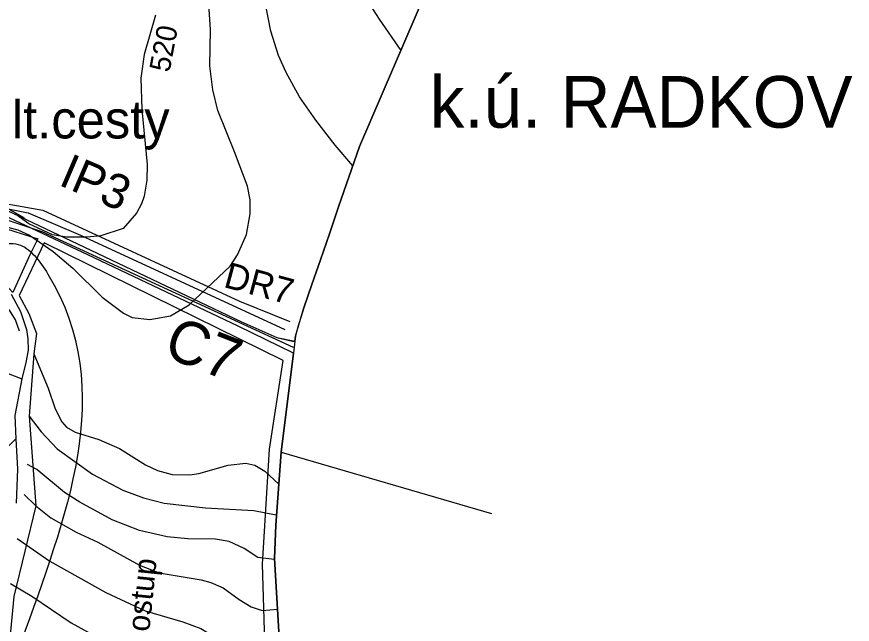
# Model space of a CAD drawing. Extents: x -684583 to -680383, y -1157874 to -1154904.
# Drawn here: x -682795.6 to -682310.9, y -1156657.4 to -1156304.8 of the extents above; entities that cross this region are included whole.
import ezdxf

# ---------------------------------------------------------------- set-up
doc = ezdxf.new("R2010")
doc.units = 0
for name, color, linetype in [('01_OBVOD PÚ', 7, 'Continuous'), ('01_SPRÁV_HRANICE', 7, 'Continuous'), ('01_VRSTEVNICE', 7, 'Continuous'), ('02_KULTURY NÁVRH', 7, 'Continuous'), ('02_KULTURY STAV', 7, 'Continuous'), ('03_PC_NÁVRH', 7, 'Continuous'), ('03_PC_OBJEKTY_NÁVRH', 7, 'Continuous'), ('03_PC_POPIS_NÁVRH', 7, 'Continuous'), ('04_ZPF_OP_ORGAN', 7, 'Continuous'), ('06_BIOGEOGRAFIE', 7, 'Continuous'), ('06_REVITALIZACE', 7, 'Continuous'), ('06_ÚSES_IP', 7, 'Continuous')]:
    doc.layers.add(name, color=color, linetype=linetype)

msp = doc.modelspace()

# ---------------------------------------------------------------- linework, layer by layer
at = {"layer": '01_OBVOD PÚ'}
for points in [[(-682557.32, -1156288.22), (-682596.72, -1156380.07), (-682608.85, -1156415.21), (-682614.21, -1156430.78), (-682619.39, -1156445.85), (-682624.47, -1156460.14), (-682629.07, -1156473.67), (-682632.75, -1156485.61), (-682633.78, -1156490.12), (-682634.17, -1156493.17), (-682635.01, -1156500.02), (-682642.14, -1156557.42)], [(-682642.14, -1156557.42), (-682645.25, -1156599.9), (-682646.11, -1156619.18), (-682640.57, -1156710.88), (-682641.16, -1156744.34), (-682654.58, -1156802.96), (-682670.79, -1156859.33), (-682678.39, -1156891.56), (-682695.23, -1156914.21), (-682697.53, -1156916.41), (-682704.08, -1156912.85), (-682712.58, -1156940.81), (-682727.9, -1157004.18), (-682712.59, -1157046.25), (-682692.26, -1157098.17), (-682680.36, -1157125.02), (-682671.31, -1157151.47), (-682668.33, -1157170.08), (-682667.92, -1157187.26), (-682669.24, -1157225.79), (-682669.43, -1157229.79), (-682672.44, -1157241.72), (-682587.6, -1157329.91)]]:
    msp.add_lwpolyline(points, dxfattribs=at)
at = {"layer": '01_SPRÁV_HRANICE'}
for points in [[(-682557.32, -1156288.22), (-682596.72, -1156380.07), (-682608.85, -1156415.21), (-682614.21, -1156430.78), (-682619.39, -1156445.85), (-682624.47, -1156460.14), (-682629.07, -1156473.67), (-682632.75, -1156485.61), (-682633.78, -1156490.12), (-682634.17, -1156493.17), (-682635.01, -1156500.02), (-682642.14, -1156557.42)], [(-682642.14, -1156557.42), (-682645.25, -1156599.9), (-682646.11, -1156619.18), (-682640.57, -1156710.88), (-682641.16, -1156744.34), (-682654.58, -1156802.96), (-682670.79, -1156859.33), (-682678.39, -1156891.56), (-682695.23, -1156914.21), (-682697.53, -1156916.41), (-682704.08, -1156912.85), (-682712.58, -1156940.81), (-682727.9, -1157004.18), (-682712.59, -1157046.25), (-682692.26, -1157098.17), (-682680.36, -1157125.02), (-682671.31, -1157151.47), (-682668.33, -1157170.08), (-682667.92, -1157187.26), (-682669.24, -1157225.79), (-682669.43, -1157229.79), (-682672.44, -1157241.72), (-682587.6, -1157329.91)], [(-682642.14, -1156557.42), (-682520.18, -1156593.07)]]:
    msp.add_lwpolyline(points, dxfattribs=at)
at = {"layer": '01_VRSTEVNICE'}
for points in [[(-682745.52, -1156093.9), (-682737.96, -1156090.76), (-682731.82, -1156090.48), (-682727.69, -1156091.9), (-682722.12, -1156095.33), (-682705.43, -1156113.73), (-682691.17, -1156131.28), (-682682.47, -1156143.26), (-682670.49, -1156161.66), (-682629.69, -1156229.13), (-682597.45, -1156287.18), (-682585.33, -1156306.3), (-682572.83, -1156324.37)], [(-682600.59, -1156391.28), (-682610.86, -1156379.33), (-682622.13, -1156364.93), (-682631.54, -1156351.23), (-682639.25, -1156337.25), (-682643.67, -1156327.27), (-682648.23, -1156313.29), (-682654.65, -1156279.34), (-682659.93, -1156261.22), (-682667.35, -1156244.82), (-682674.34, -1156232.12), (-682684.18, -1156218.72), (-682703.58, -1156199.46), (-682710.28, -1156191.9), (-682725.97, -1156171.36), (-682734.82, -1156162.94), (-682739.95, -1156159.8), (-682748.51, -1156156.09), (-682759.5, -1156154.1), (-682766.77, -1156155.52), (-682772.48, -1156158.52), (-682778.18, -1156163.37), (-682789.45, -1156159.23)], [(-682805.57, -1156425.83), (-682795.01, -1156428.4), (-682788.17, -1156431.54), (-682774.47, -1156441.1), (-682763.06, -1156450.8), (-682746.09, -1156467.49), (-682733.68, -1156476.9), (-682728.54, -1156479.33), (-682718.27, -1156480.47), (-682706.29, -1156478.33), (-682695.45, -1156472.05), (-682671.77, -1156449.51), (-682667.49, -1156442.95), (-682662.35, -1156431.11), (-682660.07, -1156419.13), (-682660.07, -1156411.14), (-682661.79, -1156403.15), (-682669.2, -1156383.18), (-682678.9, -1156359.22), (-682681.75, -1156347.24), (-682683.61, -1156333.26), (-682683.18, -1156312.15), (-682684.89, -1156286.19)], [(-682715.13, -1156303.87), (-682721.7, -1156326.7), (-682723.55, -1156340.39), (-682722.98, -1156358.65), (-682719.84, -1156390.6), (-682720.13, -1156399.73), (-682721.7, -1156408.86), (-682723.12, -1156413.42), (-682726.1, -1156418.88), (-682733.92, -1156427.73), (-682746.8, -1156431.97), (-682754.79, -1156432.68), (-682766.77, -1156432.68), (-682774.76, -1156431.4), (-682788.45, -1156424.98), (-682796.3, -1156419.41)], [(-682793.87, -1156487.31), (-682796.3, -1156480.75), (-682799.72, -1156475.19), (-682804.29, -1156469.91), (-682806.71, -1156468.34), (-682814.7, -1156465.35), (-682819.83, -1156464.92), (-682825.11, -1156465.63)], [(-682785.65, -1156500.47), (-682777.33, -1156520.41), (-682773.19, -1156532.39), (-682769.34, -1156539.95), (-682766.77, -1156543.09), (-682761.64, -1156545.94), (-682747.94, -1156550.22), (-682735.96, -1156555.35), (-682720.84, -1156564.77), (-682713.99, -1156568.19), (-682705.43, -1156570.47), (-682695.16, -1156570.62), (-682690.03, -1156569.9), (-682672.91, -1156565.05), (-682662.64, -1156563.91), (-682657.51, -1156565.05), (-682651.66, -1156568.48), (-682643.5, -1156576.03)], [(-682788.37, -1156536.68), (-682781.46, -1156545.65), (-682772.19, -1156555.64), (-682751.65, -1156570.33), (-682733.96, -1156579.6), (-682721.98, -1156584.03), (-682710, -1156587.02), (-682686.04, -1156589.88), (-682658.08, -1156591.3), (-682644.98, -1156593.84)], [(-682646.14, -1156619.75), (-682655.79, -1156618.55), (-682663.64, -1156613.41), (-682672.34, -1156609.28), (-682680.33, -1156607.99), (-682696.3, -1156607.71), (-682708.29, -1156606.56), (-682724.26, -1156603), (-682740.24, -1156596.72), (-682758.93, -1156586.59), (-682767.77, -1156580.89), (-682783.89, -1156567.48), (-682789.34, -1156564.7)], [(-682791.23, -1156582.13), (-682784.46, -1156588.73), (-682775.76, -1156595.58), (-682761.07, -1156604), (-682748.51, -1156609.7), (-682724.26, -1156623.11), (-682712.85, -1156627.53), (-682688.6, -1156631.53), (-682682.9, -1156633.1), (-682675.91, -1156636.23), (-682666.63, -1156643.08), (-682659.5, -1156647.22), (-682653.23, -1156649.36), (-682644.33, -1156648.57)], [(-682795.26, -1156607.53), (-682776.33, -1156620.69), (-682743.95, -1156638.94), (-682721.12, -1156649.5), (-682699.16, -1156655.92), (-682688.74, -1156659.91), (-682666.63, -1156673.32), (-682657.79, -1156674.46), (-682654.65, -1156673.75), (-682651.23, -1156671.47), (-682647.66, -1156670.61), (-682645.38, -1156673.32), (-682644.81, -1156677.6), (-682644.95, -1156690.44), (-682640.49, -1156712.13)], [(-682799.14, -1156633.78), (-682786.88, -1156641.08), (-682763.92, -1156656.63), (-682743.38, -1156668.04), (-682727.4, -1156674.6), (-682711.42, -1156679.74), (-682687.46, -1156686.02), (-682675.05, -1156691.01), (-682666.35, -1156697.29), (-682664.21, -1156699.57), (-682660.07, -1156706.41), (-682658.36, -1156710.98), (-682656.65, -1156720.11), (-682657.51, -1156744.93), (-682655.51, -1156761.9), (-682655.51, -1156767.47), (-682657.51, -1156777.74), (-682660.5, -1156786.3), (-682661.93, -1156792.86), (-682662.88, -1156799.77), (-682662.11, -1156829.16)]]:
    msp.add_lwpolyline(points, dxfattribs=at)
at = {"layer": '02_KULTURY NÁVRH'}
for points in [[(-682887.91, -1156417.72), (-682866.23, -1156419.79), (-682828.98, -1156422.33), (-682806.49, -1156426.37), (-682783.26, -1156433.67), (-682787.89, -1156443.08), (-682788.73, -1156444.69), (-682797.87, -1156464.81), (-682800.21, -1156462.31), (-682802.73, -1156459.5), (-682869.24, -1156422.91), (-682878.07, -1156420.23)], [(-682811.55, -1156507.67), (-682792.62, -1156514.96), (-682796.58, -1156536.16), (-682796.03, -1156549.68), (-682806.13, -1156559.58), (-682825.6, -1156557.59), (-682824.2, -1156541.34)]]:
    msp.add_lwpolyline(points, close=True, dxfattribs=at)
at = {"layer": '02_KULTURY STAV'}
for points in [[(-682837.34, -1156293.13), (-682860.97, -1156340.11), (-682865.88, -1156349.21), (-682879.26, -1156381.53), (-682886.9, -1156409.8), (-682882.56, -1156409.71), (-682869.55, -1156406.81), (-682851.47, -1156397.34), (-682840.47, -1156400.15), (-682828.26, -1156404.5), (-682752.66, -1156440.28), (-682665.48, -1156481.67), (-682644.77, -1156490.96), (-682634.17, -1156493.17), (-682633.78, -1156490.12), (-682629.07, -1156473.67), (-682624.47, -1156460.14), (-682619.39, -1156445.85), (-682614.21, -1156430.78), (-682608.85, -1156415.21), (-682596.72, -1156380.07), (-682557.32, -1156288.22)], [(-682640.57, -1156710.88), (-682646.11, -1156619.18), (-682645.25, -1156599.9), (-682642.14, -1156557.42), (-682635.01, -1156500.02), (-682667.07, -1156484.3), (-682754.25, -1156442.99), (-682829.25, -1156407.8)], [(-682798.7, -1156465.79), (-682793.43, -1156475.86), (-682789.98, -1156486.39), (-682789.16, -1156491.7), (-682788.94, -1156498.27), (-682790.31, -1156505.5), (-682792.62, -1156514.96), (-682796.58, -1156536.16)], [(-682798.7, -1156465.79), (-682793.43, -1156475.86), (-682789.98, -1156486.39), (-682789.16, -1156491.7), (-682788.94, -1156498.27), (-682790.31, -1156505.5), (-682792.62, -1156514.96), (-682796.58, -1156536.16)], [(-682796.03, -1156549.68), (-682795.1, -1156567.41), (-682795.87, -1156587.1)], [(-682796.03, -1156549.68), (-682795.1, -1156567.41), (-682795.87, -1156587.1)]]:
    msp.add_lwpolyline(points, dxfattribs=at)
msp.add_lwpolyline([(-682889.47, -1156417.03), (-682886.9, -1156409.8), (-682885.02, -1156409.17), (-682882.56, -1156409.71), (-682869.55, -1156406.81), (-682851.47, -1156397.34), (-682840.47, -1156400.15), (-682828.26, -1156404.5), (-682752.66, -1156440.28), (-682665.48, -1156481.67), (-682644.77, -1156490.96), (-682635.67, -1156493), (-682634.17, -1156493.17), (-682635.01, -1156500.02), (-682667.07, -1156484.3), (-682754.25, -1156442.99), (-682829.25, -1156407.8), (-682850.76, -1156400.72), (-682868.28, -1156409.71), (-682880.84, -1156413.58), (-682887.91, -1156417.72)], close=True, dxfattribs=at)
at = {"layer": '03_PC_NÁVRH'}
msp.add_lwpolyline([(-682887.94, -1156412.25), (-682866.49, -1156415.4), (-682828.6, -1156417.26), (-682802.44, -1156422.27), (-682780.99, -1156429.42), (-682635.3, -1156496.52)], dxfattribs=at)
at = {"layer": '03_PC_OBJEKTY_NÁVRH'}
msp.add_lwpolyline([(-682878.05, -1156408.2), (-682845.44, -1156408.2), (-682823.88, -1156411.7), (-682788.84, -1156418.72), (-682758.65, -1156431.66), (-682640.05, -1156486.4)], dxfattribs=at)
at = {"layer": '04_ZPF_OP_ORGAN'}
msp.add_lwpolyline([(-682779.67, -1156436.1), (-682794.2, -1156466.69), (-682788.61, -1156477.13), (-682784.14, -1156488.69), (-682785.65, -1156500.47), (-682788.37, -1156536.68), (-682784.46, -1156588.73), (-682797.19, -1156641.23), (-682810.23, -1156775.49), (-682822.53, -1156859.77), (-682834.09, -1156965.69), (-682838.67, -1157072.57), (-682735.79, -1157152.27), (-682675.08, -1157204.91), (-682675.48, -1157169.72), (-682684.88, -1157129.04), (-682735.36, -1157001.81), (-682708.95, -1156906.13), (-682698.09, -1156909.32), (-682682.43, -1156889.14), (-682649.29, -1156744.14), (-682652.93, -1156622.47), (-682648.88, -1156555.77), (-682641, -1156504.41)], close=True, dxfattribs=at)
at = {"layer": '06_BIOGEOGRAFIE'}
for points in [[(-682624.87, -1154935.44), (-682669.05, -1155140.04), (-682739.65, -1155253.72), (-682834.36, -1155382.91), (-682941.12, -1155661.96), (-683008.28, -1155760.14), (-683056.49, -1155810.09), (-683084.04, -1155808.37), (-683154.45, -1155886.49), (-683231.94, -1156062.19), (-683280.08, -1156211.64), (-683362.74, -1156430.39), (-683497.05, -1156731.83), (-683541.82, -1156781.78), (-683638.25, -1156792.12), (-683701.96, -1156768), (-683817.33, -1156693.94)], [(-682820.52, -1156443.86), (-682794.69, -1156436.97), (-682777.47, -1156454.19), (-682792.96, -1156667.78), (-682801.57, -1156726.35), (-682792.96, -1156755.63), (-682811.91, -1156802.14), (-682839.46, -1156886.54), (-682887.67, -1157000.23), (-682920.39, -1157038.12)]]:
    msp.add_spline(points, degree=3, dxfattribs=at)
at = {"layer": '06_REVITALIZACE'}
msp.add_lwpolyline([(-682878.47, -1156407.84), (-682850.28, -1156394.53), (-682815.93, -1156407.44), (-682791.31, -1156421.54)], dxfattribs=at)
at = {"layer": '06_ÚSES_IP'}
msp.add_lwpolyline([(-682861.35, -1156402.68), (-682780.44, -1156417.1), (-682666.3, -1156469.98), (-682637.06, -1156481.6)], dxfattribs=at)

# ---------------------------------------------------------------- texts
at = {"layer": '01_SPRÁV_HRANICE'}
msp.add_text('k.ú. RADKOV', height=30, dxfattribs=at).set_placement((-682555.94, -1156369.22))
at = {"layer": '01_VRSTEVNICE'}
msp.add_text('520', height=12, rotation=79.3293, dxfattribs=at).set_placement((-682706.98, -1156337.49))
at = {"layer": '03_PC_OBJEKTY_NÁVRH'}
msp.add_text('DR7', height=15, rotation=344.8954, dxfattribs=at).set_placement((-682676.18, -1156461.55))
at = {"layer": '03_PC_POPIS_NÁVRH'}
msp.add_text('C7', height=25, rotation=338.5895, dxfattribs=at).set_placement((-682711.48, -1156501.37))
at = {"layer": '04_ZPF_OP_ORGAN'}
msp.add_text('PEO1,osev.postup', height=13, rotation=84.1125, dxfattribs=at).set_placement((-682729.21, -1156763.92))
at = {"layer": '06_REVITALIZACE'}
msp.add_text('rekult.cesty', height=22, dxfattribs=at).set_placement((-682855.64, -1156375.46))
at = {"layer": '06_ÚSES_IP'}
msp.add_text('IP3', height=20, rotation=336.7939, dxfattribs=at).set_placement((-682771.97, -1156402.19))

doc.saveas('drawing.dxf')
